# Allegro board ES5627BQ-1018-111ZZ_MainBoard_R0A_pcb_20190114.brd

Outline 269.65 x 263.7 mm; copper layers: TOP, G2, V3, G4, S5, G6, S7, G8, S9, G10, G11, S12, G13, S14, G15, S16, G17, V18, G19, BOTTOM. Coordinates in mm from the lower left corner of the outline.
Outline path: circle c5.87,182.28 r1.75 ; circle c7.2,256.7 r1.75 ; circle c7.2,72.2 r1.5 ; circle c30.3,216.7 r1.75 ; circle c90.07,249.68 r2.11 ; circle c91.46,145.41 r1.75 ; circle c98.58,71.61 r1.75 ; circle c129.84,140.5 r1.75 ; circle c129.84,227.5 r1.75 ; circle c139.67,112.11 r1.75 ; circle c139.67,86.07 r1.75 ; circle c144.65,258.7 r1.75 ; circle c163.36,207.2 r1.75 ; circle c191.36,163.2 r1.75 ; circle c200.12,112.11 r1.75 ; circle c200.12,86.07 r1.75 ; circle c205.84,140.5 r1.75 ; circle c216.84,227.5 r1.75 ; circle c246.84,227.5 r1.75 ; circle c246.84,140.5 r1.75 ; circle c264.65,258.7 r1.75 ; circle c264.65,178.7 r1.75 ; circle c264.65,98.7 r1.75 ; circle c264.95,52.61 r1.5 ; 265.13,257.02 262.97,259.18 ; 0,262.5 arc(0.35,263.35) 1.2,263.7 268.45,263.7 arc(269.3,263.35) 269.65,262.5 269.65,1.2 arc(269.3,0.35) 268.45,0 219.3,0 219.3,4.8 arc(218.95,5.65) 218.1,6 200.77,6 199.7,7.27 arc(199.02,7.58) 198.56,7 198.56,4.8 197.36,3 113.41,3 112.21,4.8 112.21,7 arc(111.61,7.6) 111.01,7 111.01,4.8 109.81,3 23.96,3 arc(23.11,3.35) 22.76,4.2 22.76,4.8 arc(22.41,5.65) 21.56,6 4.5,6 arc(3.65,5.65) 3.3,4.8 3.3,0 1.2,0 arc(0.35,0.35) 0,1.2 0,262.5

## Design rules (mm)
net group 1PPS_OUT_N: nets 1PPS_OUT_N 1PPS_OUT_N_R
net group 1PPS_OUT_P: nets 1PPS_OUT_P 1PPS_OUT_P_R
net group 1PPS_OUT_P_A: nets 1PPS_OUT_N_A 1PPS_OUT_P_A
net group 1PPS_RESERVE: nets 1PPS_RESERVE 1PPS_RESERVE_R
net group 1588_UART_FROM_CPU: nets 1588_CPU_OUT 1588_UART_FROM_CPU
net group 1588_UART_TO_CPU: nets 1588_TO_CPU 1588_UART_TO_CPU
net group 33931_SCL_R: nets 33931_SCL 33931_SCL_R
net group 33931_SDA_R: nets 33931_SDA 33931_SDA_R
net group 88470_1588_I2C_SDA: nets 88470_1588_I2C_SDA MAC_CPU_I2C_SDA
net group 88470_I2C_SCL: nets 88470_I2C_SCL 88470_I2C_SCL_R
net group BCM88470_LED_CLK: nets BCM88470_LED_CLK IP_LED_CLK0
net group BCM88470_LED_DATA: nets BCM88470_LED_DATA IP_LED_DATA0
net group BITS_XFMR_TTIP: nets BITS_TTIP BITS_XFMR_TTIP
net group BOOT9_5: nets BOOT9_5 BOOT__R8_5_R
net group BOOT9_6: nets BOOT9_6 BOOT__R8_6_R
net group BU_CPLD2_TDO: nets BU_CPLD2_TDO BU_CPLD2_TDO_R
net group BUS_DDRA-CLK: nets DDRA_CK_N DDRA_CK_P
net group BUS_DDRA-CMD: nets DDRA_ALERT0 DDRA_ALERT1
net group BUS_DDRB-CLK: nets DDRB_CK_N DDRB_CK_P
net group BUS_DDRB-CMD: nets DDRB_ALERT0 DDRB_ALERT1
net group BUS_DDRC-CLK: nets DDRC_CK_N DDRC_CK_P
net group BUS_DDRC-CMD: nets DDRC_ALERT0 DDRC_ALERT1
net group CLK_BITS_OSC_MCLK: nets CLK_BITS_OSC_MCLK CLK_BITS_OSC_R
net group CLS_GND: nets MGMT_PHY_MDI_N0_R MGMT_PHY_MDI_P0_R
net group CONN_JTAG_TCK: nets CONN_JTAG_TCK JTAG_TCK
net group CONN_JTAG_TDI: nets CONN_JTAG_TDI JTAG_TDO
net group CONN_JTAG_TDO: nets CONN_JTAG_TDO JTAG_TDI
net group CPLD1_TCK_R: nets CPLD1_TCK_R FPGA_JTAG_TCK
net group CPLD1_TMS_R: nets CPLD1_TMS_R FPGA_JTAG_TMS
net group CPLD2_25M_OUT_R: nets CPLD2_25M_OUT CPLD2_25M_OUT_R
net group CPLD2_TDO: nets CPLD2_TDO JTAG_CPLD2_TDO_R
net group CPLD_VDD1P8_PG_R: nets CPLD_VDD1P8_PG CPLD_VDD1P8_PG_R
net group CPLL_25M_R_CLK_N: nets CPLL_25M_R_CLK_N CPLL_25M_REFCLK_N
net group CPLL_25M_R_CLK_P: nets CPLL_25M_R_CLK_P CPLL_25M_REFCLK_P
net group CPU_CTS_N: nets CPU_CTS_N CPU_CTS_N_A
net group CPU_FPGA_PCIE_REFCLK_N: nets CPU_FPGA_PCIE_REFCLK_N N63368769
net group CPU_FPGA_PCIE_REFCLK_P: nets CPU_FPGA_PCIE_REFCLK_P N63368767
net group CPU_MPHY_MDC: nets CPU_MPHY_MDC CPU_MPHY_MDC_R
net group CPU_MPHY_MDIO: nets CPU_MPHY_MDIO CPU_MPHY_MDIO_R
net group CPU_RS232_C1+: nets CPU_RS232_C1+ CPU_RS232_C1-
net group CPU_RS232_C2+: nets CPU_RS232_C2+ CPU_RS232_C2-
net group CPU_RS232_TXD: nets CPU_RS232_TXD FPGA_UART1_TX
net group CPU_RTS_N: nets CPU_RTS_N CPU_RTS_N_A
net group CPU_RXD: nets CPU_RXD CPU_RXD_A
net group CPU_TXD: nets CPU_TXD CPU_TXD_A
net group DDR_GEN_XTAL_OUT: nets DDR_GEN_XTAL_OUT DDR_GEN_XTAL_OUT_R
net group DIFF_1PPS_OUT__A_R: nets 1PPS_OUT_N_A_R 1PPS_OUT_P_A_R
net group DIFF_HSDAC_: nets HSDAC_N HSDAC_P
net group DIFF_MGMT_PHY_MDI: nets MGMT_PHY_MDI_N3_R MGMT_PHY_MDI_P3_R
net group DIFF_NIF__RX00: nets NIF_N_RX00 NIF_P_RX00
net group DIFF_NIF__RX01: nets NIF_N_RX01 NIF_P_RX01
net group DIFF_NIF__RX02: nets NIF_N_RX02 NIF_P_RX02
net group DIFF_NIF__RX03: nets NIF_N_RX03 NIF_P_RX03
net group DIFF_NIF__RX04: nets NIF_N_RX04 NIF_P_RX04
net group DIFF_NIF__RX05: nets NIF_N_RX05 NIF_P_RX05
net group DIFF_NIF__RX06: nets NIF_N_RX06 NIF_P_RX06
net group DIFF_NIF__RX07: nets NIF_N_RX07 NIF_P_RX07
net group DIFF_NIF__TX00: nets NIF_N_TX00 NIF_P_TX00
net group DIFF_NIF__TX01: nets NIF_N_TX01 NIF_P_TX01
net group DIFF_NIF__TX02: nets NIF_N_TX02 NIF_P_TX02
net group DIFF_NIF__TX03: nets NIF_N_TX03 NIF_P_TX03
net group DIFF_NIF__TX04: nets NIF_N_TX04 NIF_P_TX04
net group DIFF_NIF__TX05: nets NIF_N_TX05 NIF_P_TX05
net group DIFF_NIF__TX06: nets NIF_N_TX06 NIF_P_TX06
net group DIFF_NIF__TX07: nets NIF_N_TX07 NIF_P_TX07
net group DIFF_NIF_RX[08]: nets NIF_RX[11]_N NIF_RX[11]_P
net group DIFF_NIF_RX[09]: nets NIF_RX[09]_N NIF_RX[09]_P
net group DIFF_NIF_RX[10]: nets NIF_RX[10]_N NIF_RX[10]_P
net group DIFF_NIF_RX[11]: nets NIF_RX[08]_N NIF_RX[08]_P
net group DIFF_NIF_RX[12]: nets NIF_RX[13]_N NIF_RX[13]_P
net group DIFF_NIF_RX[13]: nets NIF_RX[15]_N NIF_RX[15]_P
net group DIFF_NIF_RX[14]: nets NIF_RX[12]_N NIF_RX[12]_P
net group DIFF_NIF_RX[15]: nets NIF_RX[14]_N NIF_RX[14]_P
net group DIFF_NIF_TX[08]: nets NIF_TX[08]_N NIF_TX[08]_P
net group DIFF_NIF_TX[09]: nets NIF_TX[09]_N NIF_TX[09]_P
net group DIFF_NIF_TX[10]: nets NIF_TX[10]_N NIF_TX[10]_P
net group DIFF_NIF_TX[11]: nets NIF_TX[11]_N NIF_TX[11]_P
net group DIFF_NIF_TX[12]: nets NIF_TX[12]_N NIF_TX[12]_P
net group DIFF_NIF_TX[13]: nets NIF_TX[13]_N NIF_TX[13]_P
net group DIFF_NIF_TX[14]: nets NIF_TX[14]_N NIF_TX[14]_P
net group DIFF_NIF_TX[15]: nets NIF_TX[15]_N NIF_TX[15]_P
net group DIFF_NIFE_RX[16]: nets NIFE_RX[16]_N NIFE_RX[16]_P
net group DIFF_NIFE_RX[17]: nets NIFE_RX[17]_N NIFE_RX[17]_P
net group DIFF_NIFE_RX[18]: nets NIFE_RX[18]_N NIFE_RX[18]_P
net group DIFF_NIFE_RX[19]: nets NIFE_RX[19]_N NIFE_RX[19]_P
net group DIFF_NIFE_RX[20]: nets NIFE_RX[20]_N NIFE_RX[20]_P
net group DIFF_NIFE_RX[21]: nets NIFE_RX[21]_N NIFE_RX[21]_P
net group DIFF_NIFE_RX[22]: nets NIFE_RX[22]_N NIFE_RX[22]_P
net group DIFF_NIFE_RX[23]: nets NIFE_RX[23]_N NIFE_RX[23]_P
net group DIFF_NIFE_RX[24]: nets NIFE_RX[24]_N NIFE_RX[24]_P
net group DIFF_NIFE_RX[25]: nets NIFE_RX[25]_N NIFE_RX[25]_P
net group DIFF_NIFE_RX[26]: nets NIFE_RX[26]_N NIFE_RX[26]_P
net group DIFF_NIFE_RX[27]: nets NIFE_RX[27]_N NIFE_RX[27]_P
net group DIFF_NIFE_TX[16]: nets NIFE_TX[16]_N NIFE_TX[16]_P
net group DIFF_NIFE_TX[17]: nets NIFE_TX[17]_N NIFE_TX[17]_P
net group DIFF_NIFE_TX[18]: nets NIFE_TX[18]_N NIFE_TX[18]_P
net group DIFF_NIFE_TX[19]: nets NIFE_TX[19]_N NIFE_TX[19]_P
net group DIFF_NIFE_TX[20]: nets NIFE_TX[20]_N NIFE_TX[20]_P
net group DIFF_NIFE_TX[21]: nets NIFE_TX[21]_N NIFE_TX[21]_P
net group DIFF_NIFE_TX[22]: nets NIFE_TX[22]_N NIFE_TX[22]_P
net group DIFF_NIFE_TX[23]: nets NIFE_TX[23]_N NIFE_TX[23]_P
net group DIFF_NIFE_TX[24]: nets NIFE_TX[24]_N NIFE_TX[24]_P
net group DIFF_NIFE_TX[25]: nets NIFE_TX[25]_N NIFE_TX[25]_P
net group DIFF_NIFE_TX[26]: nets NIFE_TX[26]_N NIFE_TX[26]_P
net group DIFF_NIFE_TX[27]: nets NIFE_TX[27]_N NIFE_TX[27]_P
net group DIFF_NIFE_TX[46]: nets 10G_KR_RX1_N 10G_KR_RX1_P
net group DIFF_NIFE_TX[47]: nets 10G_KR_RX0_N 10G_KR_RX0_P
net group DIFF_THERMAL_DIODE__R: nets THERMAL_DIODE_N_R THERMAL_DIODE_P_R
net group DIFFPAIR1: nets MGMT_PHY_MDI_N2_R MGMT_PHY_MDI_P2_R
net group DIFFPAIR2: nets MGMT_PHY_MDI_N1_R MGMT_PHY_MDI_P1_R
net group DIFFPAIR4: nets MGMT_MDI_N0_GE MGMT_MDI_P0_GE
net group DIFFPAIR5: nets MGMT_MDI_N1_GE MGMT_MDI_P1_GE
net group DIFFPAIR6: nets MGMT_MDI_N2_GE MGMT_MDI_P2_GE
net group DIFFPAIR7: nets MGMT_MDI_N3_GE MGMT_MDI_P3_GE
net group DIFFPAIR8: nets RJ_STACKING_SYNC_N0 RJ_STACKING_SYNC_P0
net group DIFFPAIR9: nets RJ_STACKING_SYNC_N1 RJ_STACKING_SYNC_P1
net group DIFFPAIR10: nets RJ_STACKING_SYNC_N2 RJ_STACKING_SYNC_P2
net group DIFFPAIR11: nets RJ_STACKING_SYNC_N3 RJ_STACKING_SYNC_P3
net group DIFFPAIR20: nets STACKING_CNTL_MDI_N3_GE STACKING_CNTL_MDI_P3_GE
net group DIFFPAIR21: nets STACKING_CNTL_MDI_N2_GE STACKING_CNTL_MDI_P2_GE
net group DIFFPAIR22: nets STACKING_CNTL_MDI_N1_GE STACKING_CNTL_MDI_P1_GE
net group DIFFPAIR23: nets STACKING_CNTL_MDI_N0_GE STACKING_CNTL_MDI_P0_GE
net group DIFFPAIR24: nets MGMT_PHY_MDI_N0 MGMT_PHY_MDI_P0
net group DIFFPAIR25: nets MGMT_PHY_MDI_N3 MGMT_PHY_MDI_P3
net group DIFFPAIR26: nets MGMT_PHY_MDI_N2 MGMT_PHY_MDI_P2
net group DIFFPAIR27: nets MGMT_PHY_MDI_N1 MGMT_PHY_MDI_P1
net group DIFFPAIR29: nets SATA0_RX_N SATA0_RX_P
net group DIFFPAIR31: nets FC1_156.25M_REFCLKN_R FC1_156.25M_REFCLKP_R
net group DIFFPAIR32: nets FC2_156.25M_REFCLKN_R FC2_156.25M_REFCLKP_R
net group DIFFPAIR33: nets FPGA_156.25M_REF_CLK_N_R FPGA_156.25M_REF_CLK_P_R
net group DIFFPAIR43: nets BITS_RRING BITS_RTIP
net group DIFFPAIR45: nets BITS_TRING_R BITS_XFMR_TTIP_R
net group DIFFPAIR46: nets BITS_RRING_R BITS_RTIP_R
net group DIFFPAIR48: nets N62472864 N62472867
net group DIFFPAIR49: nets USB2_N USB2_P
net group DIFFPAIR50: nets CPU_FPGA_PCIE_TX_N CPU_FPGA_PCIE_TX_P
net group DIFFPAIR53: nets N62747426 N62747432
net group DIFFPAIR54: nets N62747438 N62747447
net group DIFFPAIR55: nets FPGA_156.25M_REF_CLK_N FPGA_156.25M_REF_CLK_P
net group DIFFPAIR58: nets P_STACKING_SYNC_N1 P_STACKING_SYNC_P1
net group DIFFPAIR59: nets P_STACKING_SYNC_N0 P_STACKING_SYNC_P0
net group DIFFPAIR60: nets P_STACKING_SYNC_N3 P_STACKING_SYNC_P3
net group DIFFPAIR61: nets P_STACKING_SYNC_N2 P_STACKING_SYNC_P2
net group DIFFPAIR62: nets FPGA_156.25M_REF_CLK_N_F FPGA_156.25M_REF_CLK_P_F
net group DP_TS_25M_REFCLK_N_R: nets TS_25M_REFCLK_N_R TS_25M_REFCLK_P_R
net group EEPROM_SCL: nets EEPROM_SCL EEPROM_SCL_R
net group EEPROM_SDA: nets EEPROM_SDA EEPROM_SDA_R
net group EN_VDD1P0_ROV: nets EN_VDD1P0_ROV VEN_VDD1P0_ROV
net group FAN_SCL_1: nets FAN_SCL_1 FAN_SCL_FPGA
net group FAN_SDA_1: nets FAN_SDA_1 FAN_SDA_FPGA
net group FAP_SYNC1: nets FAP_SYNC1 FAP_SYNC1_R
net group FAP_TIME_VAL0: nets FAP_TIME_VAL0 FAP_TIME_VAL0_R
net group FAP_TIME_VAL1: nets FAP_TIME_VAL1 FAP_TIME_VAL1_R
net group FAP_TS_BIT_CLK0: nets FAP_TS_BIT_CLK0 TS_BIT_CLK0_R
net group FAP_TS_BIT_CLK1: nets FAP_TS_BIT_CLK1 TS_BIT_CLK1_R
net group FPGA_CPU_PCIE_RX_N: nets FPGA_CPU_PCIE_RX_N FPGA_CPU_PCIE_RX_N_F
net group FPGA_CPU_PCIE_RX_P: nets FPGA_CPU_PCIE_RX_P FPGA_CPU_PCIE_RX_P_F
net group FPGA_JTAG_TDO: nets FPGA_JTAG_TDO JTAG_CPLD2_TDI
net group GPS_UART_RX: nets GPS_UART_RX GPS_UART_RX_R
net group I2C_0_SCL_CPLD2: nets I2C_0_SCL_CPLD2 I2C_0_SCL_SWITCH_CPLD2_R
net group I2C_0_SCL_SWITCH_CPLD1_R: nets I2C_0_SCL_CPLD1 I2C_0_SCL_SWITCH_CPLD1_R
net group I2C_0_SDA: nets I2C_0_SDA I2C_0_SDA_R
net group I2C_1_SDA: nets I2C_1_SDA I2C_1_SDA_R
net group L1_RCVRD_CLK: nets L1_RCVRD_CLK L1_RCVRD_CLK_R
net group L1_RCVRD_CLK_BKUP: nets L1_RCVRD_CLK_BKUP L1_RCVRD_CLK_BKUP_R
net group L1_RCVRD_CLK_BKUP_G: nets L1_RCVRD_CLK_BKUP_G L1_RCVRD_CLK_BKUP_GR
net group L1_RCVRD_CLK_G: nets L1_RCVRD_CLK_G L1_RCVRD_CLK_GR
net group L1_RCVRD_CLK_VALID: nets L1_RCVRD_CLK_VALID L1_RCVRD_CLK_VALID_R
net group L1_RCVRD_CLK_VALID_BKUP: nets L1_RCVRD_CLK_VALID_BKUP L1_RCVRD_CLK_VALID_BKUP_R
net group LED_LINK1000: nets LED_LINK1000 MGMT_PHY_LINK_LED
net group LED_TX: nets LED_TX MGMT_PHY_ACT_LED
net group LM75BD1_INT: nets LM75BD1_INT LM75BD1_INT_R
net group LM75BD1_SCLK_R: nets LM75BD1_SCLK LM75BD1_SCLK_R
net group LM75BD1_SDA: nets LM75BD1_SDA LM75BD1_SDA_R
net group LM75BD2_INT: nets LM75BD2_INT LM75BD2_INT_R
net group LM75BD2_SDA: nets LM75BD2_SDA LM75BD2_SDA_R
net group LM75BD3_INT: nets LM75BD3_INT LM75BD3_INT_R
net group LM75BD3_SCLK_R: nets LM75BD3_SCLK LM75BD3_SCLK_R
net group LM75BD3_SDA: nets LM75BD3_SDA LM75BD3_SDA_R
net group MAC_25M_OUT: nets MAC_25M_OUT MAC_25M_OUT_R
net group MAC_JTAG_TCK: nets MAC_JTAG_TCK MAC_TCK
net group MAC_NIF_156.25M_N: nets MAC_NIF_156.25M_N NIF_156.25M_N
net group MAC_NIF_156.25M_P: nets MAC_NIF_156.25M_P NIF_156.25M_P
net group MAC_NIFE1_156.25M_N: nets MAC_NIFE1_156.25M_N NIFE1_156.25M_N
net group MAC_NIFE1_156.25M_P: nets MAC_NIFE1_156.25M_P NIFE1_156.25M_P
net group MAC_PCIE_100M_MAC_N: nets MAC_PCIE_100M_MAC_N MAC_PCIE_100M_N
net group MAC_PCIE_100M_MAC_P: nets MAC_PCIE_100M_MAC_P MAC_PCIE_100M_P
net group MAC_TDO: nets MAC_JTAG_TDO MAC_TDO
net group MAC_TRST: nets MAC_TCE MAC_TRST
net group MANG_1P2_PG_R: nets MANG_1P2_PG MANG_1P2_PG_R
net group MGMT_MDI_N0: nets MGMT_MDI_N0 MGMT_MDI_N0_R
net group MGMT_MDI_N1: nets MGMT_MDI_N1 MGMT_MDI_N1_R
net group MGMT_MDI_N2: nets MGMT_MDI_N2 MGMT_MDI_N2_R
net group MGMT_MDI_N3: nets MGMT_MDI_N3 MGMT_MDI_N3_R
net group MGMT_MDI_P0: nets MGMT_MDI_P0 MGMT_MDI_P0_R
net group MGMT_MDI_P1: nets MGMT_MDI_P1 MGMT_MDI_P1_R
net group MGMT_MDI_P2: nets MGMT_MDI_P2 MGMT_MDI_P2_R
net group MGMT_MDI_P3: nets MGMT_MDI_P3 MGMT_MDI_P3_R
net group NIFE_RX[32]: nets NIFE_RX[32]_N NIFE_RX[32]_P
net group NIFE_RX[33]: nets NIFE_RX[33]_N NIFE_RX[33]_P
net group NIFE_RX[34]: nets NIFE_RX[34]_N NIFE_RX[34]_P
net group NIFE_RX[35]: nets NIFE_RX[35]_N NIFE_RX[35]_P
net group NIFE_RX[36]: nets NIFE_RX[36]_N NIFE_RX[36]_P
net group NIFE_RX[37]: nets NIFE_RX[37]_N NIFE_RX[37]_P
net group NIFE_RX[38]: nets NIFE_RX[38]_N NIFE_RX[38]_P
net group NIFE_RX[39]: nets NIFE_RX[39]_N NIFE_RX[39]_P
net group NIFE_RX[46]_N: nets 10G_KR_TX1_N NIFE_RX[46]_N
net group NIFE_RX[46]_P: nets 10G_KR_TX1_P NIFE_RX[46]_P
net group NIFE_RX[47]_N: nets 10G_KR_TX0_N NIFE_RX[47]_N
net group NIFE_RX[47]_P: nets 10G_KR_TX0_P NIFE_RX[47]_P
net group NIFE_TX[32]: nets NIFE_TX[32]_N NIFE_TX[32]_P
net group NIFE_TX[33]: nets NIFE_TX[33]_N NIFE_TX[33]_P
net group NIFE_TX[34]: nets NIFE_TX[34]_N NIFE_TX[34]_P
net group NIFE_TX[35]: nets NIFE_TX[35]_N NIFE_TX[35]_P
net group NIFE_TX[36]: nets NIFE_TX[36]_N NIFE_TX[36]_P
net group NIFE_TX[37]: nets NIFE_TX[37]_N NIFE_TX[37]_P
net group NIFE_TX[38]: nets NIFE_TX[38]_N NIFE_TX[38]_P
net group NIFE_TX[39]: nets NIFE_TX[39]_N NIFE_TX[39]_P
net group OCXO25MHZ: nets OCXO25MHZ OCXO25MHZ_R
net group PEX_CPU_PCIEA_RX_0_N: nets PEX_CPU_PCIEA_RX_0_C_N PEX_CPU_PCIEA_RX_0_N
net group PEX_CPU_PCIEA_RX_0_P: nets PEX_CPU_PCIEA_RX_0_C_P PEX_CPU_PCIEA_RX_0_P
net group PHY_TDI: nets PHY_TDI PHY_TDI_R
net group PHY_TDO: nets PHY_TDO PHY_TDO_R
net group PM_VDDQ_EN_R: nets PM_VDDQ_EN_R VEN_VDD0P6
net group PSU1_SCL: nets PSU1_SCL PSU1_SCL_R
net group PSU1_SDA: nets PSU1_SDA PSU1_SDA_R
net group PSU2_SCL: nets PSU2_SCL PSU2_SCL_R
net group PSU2_SDA: nets PSU2_SDA PSU2_SDA_R
net group PSU_MONITOR_SCL: nets PSU_MONITOR_SCL PSU_MONITOR_SCL_R
net group QSFP_INT_P02: nets QSFP_INT_P02 QSFP_INT_P02_R
net group QSFP_INT_P03: nets QSFP_INT_P03 QSFP_INT_P03_R
net group QSFP_P01_SCL: nets QSFP_P01_SCL QSFP_P01_SCL_R
net group QSFP_P01_SDA_R: nets QSFP_P01_SDA QSFP_P01_SDA_R
net group QSFP_P02_SCL: nets QSFP_P02_SCL QSFP_P02_SCL_R
net group QSFP_P02_SDA_R: nets QSFP_P02_SDA QSFP_P02_SDA_R
net group SFP+_P01_SCL_R: nets SFP+_P01_SCL SFP+_P01_SCL_R
net group SFP+_P01_SDA_R: nets SFP+_P01_SDA SFP+_P01_SDA_R
net group SFP+_P02_SCL_R: nets SFP+_P02_SCL SFP+_P02_SCL_R
net group SFP+_P02_SDA_R: nets SFP+_P02_SDA SFP+_P02_SDA_R
net group SFP+_P03_SCL_R: nets SFP+_P03_SCL SFP+_P03_SCL_R
net group SFP+_P03_SDA_R: nets SFP+_P03_SDA SFP+_P03_SDA_R
net group SFP+_P04_SCL_R: nets SFP+_P04_SCL SFP+_P04_SCL_R
net group SFP+_P04_SDA_R: nets SFP+_P04_SDA SFP+_P04_SDA_R
net group SFP+_P05_SCL_R: nets SFP+_P05_SCL SFP+_P05_SCL_R
net group SFP+_P05_SDA_R: nets SFP+_P05_SDA SFP+_P05_SDA_R
net group SFP+_P06_SCL_R: nets SFP+_P06_SCL SFP+_P06_SCL_R
net group SFP+_P06_SDA_R: nets SFP+_P06_SDA SFP+_P06_SDA_R
net group SFP+_P07_SCL_R: nets SFP+_P07_SCL SFP+_P07_SCL_R
net group SFP+_P07_SDA_R: nets SFP+_P07_SDA SFP+_P07_SDA_R
net group SFP+_P08_SCL_R: nets SFP+_P08_SCL SFP+_P08_SCL_R
net group SFP+_P08_SDA_R: nets SFP+_P08_SDA SFP+_P08_SDA_R
net group SFP+_P09_SCL_R: nets SFP+_P09_SCL SFP+_P09_SCL_R
net group SFP+_P09_SDA_R: nets SFP+_P09_SDA SFP+_P09_SDA_R
net group SFP+_P10_SCL_R: nets SFP+_P10_SCL SFP+_P10_SCL_R
net group SFP+_P10_SDA_R: nets SFP+_P10_SDA SFP+_P10_SDA_R
net group SFP+_P11_SCL_R: nets SFP+_P11_SCL SFP+_P11_SCL_R
net group SFP+_P11_SDA_R: nets SFP+_P11_SDA SFP+_P11_SDA_R
net group SFP+_P12_SCL_R: nets SFP+_P12_SCL SFP+_P12_SCL_R
net group SFP+_P12_SDA_R: nets SFP+_P12_SDA SFP+_P12_SDA_R
net group SFP+_P13_SCL_R: nets SFP+_P13_SCL SFP+_P13_SCL_R
net group SFP+_P13_SDA_R: nets SFP+_P13_SDA SFP+_P13_SDA_R
net group SFP+_P14_SCL_R: nets SFP+_P14_SCL SFP+_P14_SCL_R
net group SFP+_P14_SDA_R: nets SFP+_P14_SDA SFP+_P14_SDA_R
net group SFP+_P15_SCL_R: nets SFP+_P15_SCL SFP+_P15_SCL_R
net group SFP+_P15_SDA_R: nets SFP+_P15_SDA SFP+_P15_SDA_R
net group SFP+_P16_SCL_R: nets SFP+_P16_SCL SFP+_P16_SCL_R
net group SFP+_P16_SDA_R: nets SFP+_P16_SDA SFP+_P16_SDA_R
net group SFP+_P17_SCL_R: nets SFP+_P17_SCL SFP+_P17_SCL_R
net group SFP+_P17_SDA_R: nets SFP+_P17_SDA SFP+_P17_SDA_R
net group SFP+_P18_SCL_R: nets SFP+_P18_SCL SFP+_P18_SCL_R
net group SFP+_P18_SDA_R: nets SFP+_P18_SDA SFP+_P18_SDA_R
net group SFP+_P19_SCL: nets SFP+_P19_SCL SFP+_P19_SCL_R
net group SFP+_P19_SDA: nets SFP+_P19_SDA SFP+_P19_SDA_R
net group SFP+_P20_SCL_R: nets SFP+_P20_SCL SFP+_P20_SCL_R
net group SFP+_P20_SDA_R: nets SFP+_P20_SDA SFP+_P20_SDA_R
net group SFP+_P21_SCL_R: nets SFP+_P21_SCL SFP+_P21_SCL_R
net group SFP+_P21_SDA_R: nets SFP+_P21_SDA SFP+_P21_SDA_R
net group SFP+_P22_SCL_R: nets SFP+_P22_SCL SFP+_P22_SCL_R
net group SFP+_P22_SDA_R: nets SFP+_P22_SDA SFP+_P22_SDA_R
net group SFP+_P23_SCL_R: nets SFP+_P23_SCL SFP+_P23_SCL_R
net group SFP+_P23_SDA_R: nets SFP+_P23_SDA SFP+_P23_SDA_R
net group SP01_P08_SCL: nets SP01_P08_SCL SP01_P08_SCL_R
net group SP09_P16_SCL: nets SP09_P16_SCL SP09_P16_SCL_R
net group SP17_P24_SCL: nets SP17_P24_SCL SP17_P24_SCL_R
net group TPS53641_SDA_R: nets TPS53641_SDA_R VCC1V0_PMB_DIO
net group TS_25M_REFCLK_MAC_N: nets TS_25M_REFCLK_MAC_N TS_25M_REFCLK_N
net group TS_25M_REFCLK_MAC_P: nets TS_25M_REFCLK_MAC_P TS_25M_REFCLK_P
net group UART1_RX: nets CPLD_UART1_RX_R UART1_RX
net group UART1_TX: nets CPU_UART1_TX_R UART1_TX
net group UART_TX+: nets UART_TX+ UART_TX+_R
net group UART_TX+_A: nets UART_TX+_A UART_TX-_A
net group UART_TX-: nets UART_TX- UART_TX-_R
net group UC_25M_R_CLK_N: nets UC_25M_R_CLK_N UC_25M_REFCLK_N
net group UC_25M_R_CLK_P: nets UC_25M_R_CLK_P UC_25M_REFCLK_P
net group UCD90160_CNTRL: nets UCD90160_CNTRL UCD90160_CNTRL_R
net group UCD90160_INT: nets UCD90160_INT UCD90160_INT_R
net group UCD90160_RESERVED: nets UCD90160_RESERVED UCD90160_RESERVED_R
net group UCD90160_RST: nets HW_RESET UCD90160_RST
net group UCD90160_SCL_R: nets UCD90160_SCL UCD90160_SCL_R
net group UCD90160_SDA_R: nets UCD90160_SDA UCD90160_SDA_R
net group USBHUB_OCS1_N: nets USB_PWRFLT_N USBHUB_OCS1_N
net group USBHUB_PRTPWR1: nets USB_PWRON_N USBHUB_PRTPWR1
net group USBHUB_SDA: nets I2C_USBHUB_SDA_R USBHUB_SDA
net group USBHUB_XTALOUT_C: nets USBHUB_XTALOUT USBHUB_XTALOUT_C
net group VCC1V0_VSN: nets TPS53647_GND_SENSE VCC1V0_VSN
net group VCC1V0_VSP: nets TPS53647_VDD_SENSE VCC1V0_VSP
net group VCC1V2_BST_C: nets VCC1V2_BST_C VCC1V2_VBST
net group VCC1V2_EN: nets VCC1V2_EN VEN_VDD1P2_DDR
net group VCC1V_ENABLE: nets VCC1V_ENABLE VEN_VDD1P0
net group VCC1V_LL_C: nets VCC1V_LL_C VCC1V_VBST
net group VCC2V5_EN: nets VCC2V5_EN VEN_VPP_DDR2P5
net group VCC3V3_PCH_EN_R: nets VCC3V3_PCH_EN_R VEN_VDD3P3
net group VCC3V3_PCH_VFB_S: nets VCC3V3_PCH_VFB_S VCC3V3_TAP
net group VDD1P25_PG_R: nets VDD1P25_PG VDD1P25_PG_R
net group VEN_VCC5P0_R: nets VEN_VCC5P0_FPGA VEN_VCC5P0_R
net group VEN_VDD1P8_R: nets VEN_VDD1P8 VEN_VDD1P8_R
net group VEN_VDD1P25_R: nets VEN_VDD1P25 VEN_VDD1P25_R
net group 88470_1588_I2C_SCL: nets 88470_1588_I2C_SCL MAC_CPU_I2C_SCL MASTER_I2C_SCL
net group BCM88470_THERM_DIODE_VDD3P3: nets BCM88470_THERM_DIODE_VDD3P3
net group BITS_CHOKE_RRING: nets BITS_RJ48_RRING
net group BITS_CHOKE_RTIP: nets BITS_RJ48_RTIP
net group BITS_CHOKE_TRING: nets BITS_RJ48_TRING
net group BITS_CHOKE_TTIP: nets BITS_RJ48_TTIP
net group BUS_CLK: nets 1PPS_FPGA_IN 25MHZ_1PPS_FPGA_IN 25MHZ_1PPS_FPGA_IN_R 25MHZ_1204 25MHZ_30773 25MHZ_30773_R BCM88470_NIF_LCPLL_BYP_CLK BCM88470_NIFE_LCPLL0_BYP_CLK BCM88470_NIFE_LCPLL1_BYP_CLK COM_LPC_CLK CPLD_RST CPU_PROCHOT FPGA_REF_CLK0 FPGA_REF_CLK0_R FPGA_REF_CLK1 FPGA_REF_CLK1_R FPGA_REF_CLK2 FPGA_REF_CLK2_R FPGA_REF_CLK3 FPGA_REF_CLK3_R FPGA_REF_CLK_OUT0 FPGA_REF_CLK_OUT1 FPGA_REF_CLK_OUT2 FPGA_REF_CLK_OUT3 FPGA_RES_CLK FPGA_RES_CLK_R FPGA_SN65C_1DE FPGA_SPI_RST_N FT2232H_RESET_N I2C_CPU0_RESET_N I2C_CPU1_RESET_N LM75BD1_SCLK_C LM75BD3_SCLK_C MAC_RESET_N MGMT_CLK_IN MGMT_CLK_IN_R N62370066 N62745262 PHY_RST_N PHY_RST_N_R PHY_TCK PHY_TCK_R PHY_TMS PHY_TMS_R PHY_TRST_N POWER_RST POWER_RST_S PSU_MONITOR_RESET_N QSFP_PRSNT_P02 RXSCLK_SET SATA0_TX_P SP01_P08_RESET_N SP09_P16_RESET_N SPI_CLK SYS_SW_RST_N TPM_RESET_N USB1_VBUS_RESET USB_RESET_N ZL30773_RST
net group BUS_CLK1: nets 2.048MHZ_BITS_RCLK_IN BITS_PCLK BITS_TCLK_R CLK_BITS_MCLK CLK_BITS_TCLK DDR_GEN_XTAL_IN FAP_TS_BIT_CLK0_FPGA FAP_TS_BIT_CLK1_FPGA USBHUB_XTALIN
net group BUS_DDRA-DATA: nets DDRA_DBI_N0 DDRA_DQS0_N DDRA_DQS0_P DDRA_DQS1_N DDRA_DQS1_P DDRA_DQS2_N DDRA_DQS2_P DDRA_DQS3_N DDRA_DQS3_P
net group BUS_DDRB-DATA: nets DDRB_DQS0_N DDRB_DQS0_P DDRB_DQS1_N DDRB_DQS1_P DDRB_DQS2_N DDRB_DQS2_P DDRB_DQS3_N DDRB_DQS3_P
net group BUS_DDRC-DATA: nets DDRC_DQS0_N DDRC_DQS0_P DDRC_DQS1_N DDRC_DQS1_P DDRC_DQS2_N DDRC_DQS2_P DDRC_DQS3_N DDRC_DQS3_P
net group BUS_I2C: nets 88470_I2C_SDA CPLD_FPGA_R_SCL CPLD_FPGA_R_SDA CPLD_FPGA_SCL CPLD_FPGA_SDA FAN_SCL_FPGA_R FAN_SDA_FPGA_R I2C_0_SCL I2C_1_SCL LM75BD2_SCLK LM75BD2_SCLK_C LM75BD2_SCLK_R QSFP_P03_SDA_R USBHUB_SCL USBHUB_SCL_R USBHUB_SDA_R VCC1V0_PMB_DIO_R
net group BUS_SPI: nets BCM88470_SPI_CLK BCM88470_SPI_MISO BCM88470_SPI_MOSI
net group CLS_BITS_S80: nets BITS_XFMR_R_RRING BITS_XFMR_R_RTIP BITS_XFMR_R_TRING BITS_XFMR_R_TTIP
net group CLS_CHASIS: nets GND_USB
net group CLS_DDRA_CTL: nets DDRA_CKE DDRA_CS_N0 DDRA_CS_N1 DDRA_ODT
net group CLS_DDRA_DATA1: nets DDRA_DBI_N1 DDRA_DQ8 DDRA_DQ9 DDRA_DQ10 DDRA_DQ11 DDRA_DQ12 DDRA_DQ13 DDRA_DQ14 DDRA_DQ15
net group CLS_DDRA_DATA2: nets DDRA_DBI_N2 DDRA_DQ16 DDRA_DQ17 DDRA_DQ18 DDRA_DQ19 DDRA_DQ20 DDRA_DQ21 DDRA_DQ22 DDRA_DQ23
net group CLS_DDRA_DATA3: nets DDRA_DBI_N3 DDRA_DQ24 DDRA_DQ25 DDRA_DQ26 DDRA_DQ27 DDRA_DQ28 DDRA_DQ29 DDRA_DQ30 DDRA_DQ31
net group CLS_DDRA_MA: nets DDRA_A0 DDRA_A1 DDRA_A2 DDRA_A3 DDRA_A4 DDRA_A5 DDRA_A6 DDRA_A7 DDRA_A8 DDRA_A9 DDRA_A10 DDRA_A11 DDRA_A12 DDRA_A13 DDRA_ACT_N DDRA_BA0 DDRA_BA1 DDRA_BG0 DDRA_CAS_N DDRA_PAR DDRA_RAS_N DDRA_RST_N DDRA_WE_N
net group CLS_DDRB_CTL: nets DDRB_CKE DDRB_CS_N0 DDRB_CS_N1 DDRB_ODT
net group CLS_DDRB_DATA0: nets DDRB_DBI_N0 DDRB_DQ0 DDRB_DQ1 DDRB_DQ2 DDRB_DQ3 DDRB_DQ4 DDRB_DQ5 DDRB_DQ6 DDRB_DQ7
net group CLS_DDRB_DATA1: nets DDRB_DBI_N1 DDRB_DQ8 DDRB_DQ9 DDRB_DQ10 DDRB_DQ11 DDRB_DQ12 DDRB_DQ13 DDRB_DQ14 DDRB_DQ15
net group CLS_DDRB_DATA2: nets DDRB_DBI_N2 DDRB_DQ16 DDRB_DQ17 DDRB_DQ18 DDRB_DQ19 DDRB_DQ20 DDRB_DQ21 DDRB_DQ22 DDRB_DQ23
net group CLS_DDRB_DATA3: nets DDRB_DBI_N3 DDRB_DQ24 DDRB_DQ25 DDRB_DQ26 DDRB_DQ27 DDRB_DQ28 DDRB_DQ29 DDRB_DQ30 DDRB_DQ31
net group CLS_DDRB_MA: nets DDRB_A0 DDRB_A1 DDRB_A2 DDRB_A3 DDRB_A4 DDRB_A5 DDRB_A6 DDRB_A7 DDRB_A8 DDRB_A9 DDRB_A10 DDRB_A11 DDRB_A12 DDRB_A13 DDRB_ACT_N DDRB_BA0 DDRB_BA1 DDRB_BG0 DDRB_CAS_N DDRB_PAR DDRB_RAS_N DDRB_RST_N DDRB_WE_N
net group CLS_DDRC_CTL: nets DDRC_CKE DDRC_CS_N0 DDRC_CS_N1 DDRC_ODT
net group CLS_DDRC_DATA0: nets DDRC_DBI_N0 DDRC_DQ0 DDRC_DQ1 DDRC_DQ2 DDRC_DQ3 DDRC_DQ4 DDRC_DQ5 DDRC_DQ6 DDRC_DQ7
net group CLS_DDRC_DATA1: nets DDRC_DBI_N1 DDRC_DQ8 DDRC_DQ9 DDRC_DQ10 DDRC_DQ11 DDRC_DQ12 DDRC_DQ13 DDRC_DQ14 DDRC_DQ15
net group CLS_DDRC_DATA2: nets DDRC_DBI_N2 DDRC_DQ16 DDRC_DQ17 DDRC_DQ18 DDRC_DQ19 DDRC_DQ20 DDRC_DQ21 DDRC_DQ22 DDRC_DQ23
net group CLS_DDRC_DATA3: nets DDRC_DBI_N3 DDRC_DQ24 DDRC_DQ25 DDRC_DQ26 DDRC_DQ27 DDRC_DQ28 DDRC_DQ29 DDRC_DQ30 DDRC_DQ31
net group CLS_DDRC_MA: nets DDRC_A0 DDRC_A1 DDRC_A2 DDRC_A3 DDRC_A4 DDRC_A5 DDRC_A6 DDRC_A7 DDRC_A8 DDRC_A9 DDRC_A10 DDRC_A11 DDRC_A12 DDRC_A13 DDRC_ACT_N DDRC_BA0 DDRC_BA1 DDRC_BG0 DDRC_CAS_N DDRC_PAR DDRC_RAS_N DDRC_RST_N DDRC_WE_N
net group CLS_I2C: nets 30773_SCL_FP 30773_SCL_FP_R 30773_SDA_FP 30773_SDA_FP_R QSFP_P03_SCL QSFP_P03_SCL_R QSFP_P03_SDA SP17_P24_RESET_N
net group CLS_JTAG: nets FPGA_JTAG_TCK_R FPGA_JTAG_TDI_R FPGA_JTAG_TDO_R FPGA_JTAG_TMS_R JTAG_BUFFER_OE_N MAC_JTAG_TCE
net group CLS_PHY_DMI: nets M_MCT1 M_MCT2 M_MCT3 M_MCT4 MCT1 MCT2 MCT3 MCT4 MDI-0 MDI-1 MDI-2 MDI-3 N61307888 N61983825
net group CLS_UART: nets MAC_UART0_RX MAC_UART0_RX_R MAC_UART0_TX_FPGA MAC_UART0_TX_FPGA_R MAC_UART0_TX_R MAC_UART1_RX MAC_UART1_RX_R MAC_UART1_TX MAC_UART1_TX_FPGA MAC_UART1_TX_R
net group CLS_VCC12: nets HEATER_VCC12
net group CONN_JTAG_TMS: nets CONN_JTAG_TMS
net group CPLD2_TCK: nets CPLD2_TCK CPLD2_TCK_R JTAG_CPLD2_TCK
net group CPLD2_TMS: nets CPLD2_TMS CPLD2_TMS_R JTAG_CPLD2_TMS
net group CPU_RS232_RXD: nets CPLD_RJ_UART_RX_R CPU_RS232_RXD RJ_UART_RX
net group DDRA_100M_REFCLK_N: nets DDR_GEN_OUT0_N DDRA_100M_N DDRA_100M_REFCLK_N
net group DDRA_100M_REFCLK_P: nets DDR_GEN_OUT0_P DDRA_100M_P DDRA_100M_REFCLK_P
net group DDRB_100M_REFCLK_N: nets DDR_GEN_OUT1_N DDRB_100M_N DDRB_100M_REFCLK_N
net group DDRB_100M_REFCLK_P: nets DDR_GEN_OUT1_P DDRB_100M_P DDRB_100M_REFCLK_P
net group DDRC_100M_REFCLK_N: nets DDR_GEN_OUT2_N DDRC_100M_N DDRC_100M_REFCLK_N
net group DDRC_100M_REFCLK_P: nets DDR_GEN_OUT2_P DDRC_100M_P DDRC_100M_REFCLK_P
net group DEFAULT: nets VEN_XFP_3V3
net group DIFFPAIR28: nets SATA0_TX_N
net group DIFFPAIR44: nets BITS_TRING
net group FCCM10_5: nets FCCM10_5 FCCM10_6 SKIP#_VCC1V0
net group FPGA_25M_REF_CLK_N: nets FPGA_25M_REF_CLK_N FPGA_25M_REF_CLK_N_F FPGA_25M_REF_CLK_N_R
net group FPGA_25M_REF_CLK_P: nets FPGA_25M_REF_CLK_P FPGA_25M_REF_CLK_P_F FPGA_25M_REF_CLK_P_R
net group I2C_0_SDA_CPLD1: nets I2C_0_SDA_CPLD1 I2C_0_SDA_CPLD1_R I2C_0_SDA_SWITCH_CPLD1_R
net group I2C_0_SDA_CPLD2: nets I2C_0_SDA_CPLD2 I2C_0_SDA_CPLD2_R I2C_0_SDA_SWITCH_CPLD2_R
net group MAC_NIFE0_156.25M_N: nets FC0_156.25M_REFCLKN_R MAC_NIFE0_156.25M_N NIFE0_156.25M_N
net group MAC_NIFE0_156.25M_P: nets FC0_156.25M_REFCLKP_R MAC_NIFE0_156.25M_P NIFE0_156.25M_P
net group NOISY: nets XFP_3V3_VDD
net group PSU_MONITOR_SDA: nets PSU_MONITOR_SDA PSU_MONITOR_SDA_R QSP01_P02_R_SDA
net group SENSITIVE: nets VCC3V3_PCH_TRIP XFP_3V3_PCH_RF XFP_3V3_PCH_TRIP
net group SP01_P08_R_SDA: nets SP01_P08_R_SDA SP01_P08_SDA SP01_P08_SDA_R
net group SP09_P16_R_SDA: nets SP09_P16_R_SDA SP09_P16_SDA SP09_P16_SDA_R
net group SP17_P24_R_SDA: nets SP17_P24_R_SDA SP17_P24_SDA SP17_P24_SDA_R
net group TPS53641_SCL_R: nets TPS53641_SCL_R VCC1V0_PMB_CLK VCC1V0_PMB_CLK_R
net group USB_DM: nets USB0_N USB_DM USBHUB_DM
net group USB_DP: nets USB0_P USB_DP USBHUB_DP
net group VDD1P2_DDR: nets VDD1P2_DDR_MON
net group XFP_3V3_PCH_EN_R: nets XFP_3V3_PCH_EN_R

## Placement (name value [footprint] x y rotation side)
C2  0.1uF/16V  [CC0402]  151.55 260.01 90 top
C3  0.1uF/16V  [CC0402]  151.55 257.98 90 top
C4  0.1uF/16V  [CC0402]  266.73 250.54 0 top
C7  0.1uF/16V  [CC0402]  151.55 259 90 top
C8  0.1uF/16V  [CC0402]  151.55 261.03 90 top
C9  0.1uF/16V  [CC0402]  265.71 250.54 0 top
C16  1nF 50V  [CC0402]  227.65 227.11 0 top
C17  0.1uF 16V  [CC0402]  228.8 227.11 180 top
C18  0.1uF 16V  [CC0402]  230.07 227.11 180 top
C19  0.1uF 16V  [CC0402]  232.02 227.11 180 top
C20  0.1uF 16V  [CC0402]  233.11 227.11 180 top
C21  0.1uF 16V  [CC0402]  234.38 227.11 180 top
C22  0.1uF 16V  [CC0402]  235.65 227.11 180 top
C23  0.1uF/16V  [CC0402]  61.61 190.05 270 top
C24  0.1uF/16V  [CC0402]  5.3 189.28 180 top
C25  0.1uF/16V  [CC0402]  70.96 222.92 0 bottom
C27  0.1uF/16V  [CC0402]  4.26 189.27 180 top
C28  0.1uF/16V  [CC0402]  193.36 169.94 180 top
C29  0.1uF 16V  [CC0402]  238.27 225.45 90 top
C30  0.1uF/16V  [CC0402]  191.33 169.97 180 top
C31  1nF /50V  [CC0402]  62.94 184.84 0 top
C32  10uF  [CC0402]  62.94 187.76 0 top
C33  0.1uF/16V  [CC0402]  192.34 169.94 180 top
C34  0.1uF/16V  [CC0402]  190.31 169.97 180 top
C35  0.1uF 16V  [CC0402]  238.21 224.44 90 top
C36  10uF  [CC0603]  63.53 182.4 0 top
C37  0.1uF/16V  [CC0402]  82.81 215.42 180 top
C38  0.1uF/16V  [CC0402]  264.7 250.54 0 top
C39  0.1uF/16V  [CC0402]  263.68 250.54 0 top
C41  10uF  [CC0603]  64.95 182.4 0 top
C42  0.1UF 50V  [CC0603]  89.8 204.26 0 top
C43  22uF/6.3V  [CC0603]  66.5 182.43 0 top
C44  0.1uF/16V  [CC0402]  62.7 223.24 180 top
C45  0.1uF 16V  [CC0402]  238.19 220.89 90 top
C47  0.1uF/16V  [CC0402]  67.64 191.83 180 top
C48  22uF  [CC0603]  80.8 213.54 270 top
C49  10uF/6.3V  [CC0603]  80.79 214.98 270 top
C50  10uF/6.3V  [CC0603]  84.2 210.49 180 top
C52  0.1uF/16V  [CC0402]  82.9 210.67 180 top
C53  0.1uF 16V  [CC0402]  238.21 219.55 90 top
C54  22uF/6.3V  [CC0603]  68.28 182.43 0 top
C55  0.1uF/16V  [CC0402]  167.39 178.58 180 top
C56  10uF/6.3V  [CC0603]  168.73 178.24 0 top
C57  0.1uF/16V  [CC0402]  153.88 244.34 90 top
C58  @10pF  [CC0402]  90.18 214.78 0 top
C59  0.1uF/16V  [CC0402]  45.75 222.86 0 bottom
C60  0.1uF/16V  [CC0402]  68.59 190.81 0 top
C61  0.1uF 16V  [CC0402]  238.21 218.21 90 top
C62  10uF/6.3V  [CC0603]  181.7 199.43 90 top
C63  1nF  [CC0402]  69.54 182.73 180 top
C64  10nF/50V  [CC0402]  69.22 185.65 90 bottom
C68  0.1uF 16V  [CC0402]  238.19 216.95 90 top
C69  0.1uF/16V  [CC0402]  181.37 198.16 90 top
C73  0.1uF/16V  [CC0402]  22.06 178.03 180 top
C74  22nF/16V  [CC0402]  22.95 178.03 0 top
C75  22nF/16V  [CC0402]  24.98 178.03 0 top
C76  0.1uF/16V  [CC0402]  26 178.03 180 top
C77  1uF/25V  [CC0402]  27.02 178.03 180 top
C78  0.01uF/25V  [CC0402]  28.03 178.03 0 top
C79  1uF/25V  [CC0402]  29.05 178.03 180 top
C80  0.1uF/16V  [CC0402]  30.09 178.03 180 top
C81  0.1uF/16V  [CC0402]  31.11 178.03 180 top
C82  10uF/10V  [CC0402]  32.12 178.03 180 top
C83  0.1uF 16V  [CC0402]  238.19 215.68 90 top
C84  0.01uF/25V  [CC0402]  69.59 177.8 0 top
C85  0.01uF/25V  [CC0402]  70.58 177.8 0 top
C86  0.1uF/16V  [CC0402]  54.32 177.77 180 top
C87  1uF/25V  [CC0402]  55.34 177.77 180 top
C88  22nF/16V  [CC0402]  60.42 177.77 0 top
C89  1uF/25V  [CC0402]  61.43 177.77 180 top
C90  1uF/25V  [CC0402]  62.45 177.77 180 top
C91  0.1uF/16V  [CC0402]  63.47 177.77 180 top
C92  0.1uF/16V  [CC0402]  64.48 177.77 180 top
C93  10uF/10V  [CC0402]  65.5 177.77 180 top
C94  1uF/25V  [CC0402]  66.51 177.77 180 top
C95  0.1uF/16V  [CC0402]  67.53 177.77 180 top
C96  0.1uF/16V  [CC0402]  68.55 177.77 180 top
C97  0.1UF 50V  [CC0603]  86.74 220.1 90 top
C99  0.1uF 16V  [CC0402]  238.19 214.41 90 top
C100  10uF/6.3V  [CC0603]  181.66 195.28 270 top
C101  @10pF  [CC0402]  184.25 194.87 90 top
C102  0.1uF/16V  [CC0402]  54.32 175.49 0 top
C104  0.1uF 16V  [CC0402]  236.67 212.64 90 top
C106  0.1uF 16V  [CC0402]  230.45 212.38 90 top
C107  0.1uF 16V  [CC0402]  232.48 212.38 90 top
C108  0.1uF/16V  [CC0402]  162.78 220.06 90 top
C109  10nF 50V  [CC0402]  233.93 212.13 0 top
C110  1uF  [CC0402]  234.92 212.13 180 top
C112  0.1UF 50V  [CC0603]  86.74 218.63 90 top
C113  0.1uF/16V  [CC0402]  75.66 174.47 270 top
C114  22uF  [CC0603]  181.66 193.63 270 top
C115  0.1UF 50V  [CC0603]  123.78 204.35 180 top
C117  0.1uF 16V  [CC0402]  230.45 211.37 90 top
C118  0.1uF 16V  [CC0402]  236.67 211.37 90 top
C119  22nF/16V  [CC0402]  75.66 173.45 90 top
C121  0.1uF/16V  [CC0402]  181.83 192.4 270 top
C122  10uF 6.3V  [CC0603]  234.1 210.12 270 top
C123  10uF 6.3V  [CC0603]  230.32 209.97 90 top
C126  10uF/10V  [CC0402]  75.66 171.42 270 top
C128  1uF/25V  [CC0402]  29.05 170.53 180 top
C129  0.1uF/16V  [CC0402]  230.57 207.68 90 top
C130  1uF/25V  [CC0402]  75.66 170.41 270 top
C131  0.01uF  [CC0402]  203.11 233.53 270 top
C132  1uF/25V  [CC0402]  46.45 170.28 0 top
C133  0.1uF/16V  [CC0402]  47.46 170.28 0 top
C134  0.1uF/16V  [CC0402]  27.14 169.64 0 top
C135  22nF/16V  [CC0402]  28.16 169.64 0 top
C136  10uF  [CC0603]  203.61 235.87 270 top
C137  10pF  [CC0402]  203.11 234.54 90 top
C139  10uF/6.3V  [CC0603]  9.49 167.04 90 top
C140  @10pF/50V  [CC0402]  6.19 167.85 270 top
C142  0.1uF/16V  [CC0402]  75.66 167.36 270 top
C143  0.01uF/25V  [CC0402]  28.54 166.93 270 top
C144  0.1uF/16V  [CC0402]  10.51 168.31 90 top
C145  0.1UF 50V  [CC0603]  129.07 216.55 180 top
C146  2.2UF  [CC0603]  200.17 237.99 90 top
C149  0.1uF/16V  [CC0402]  28.54 165.91 270 top
C151  1uF/25V  [CC0402]  26.38 165.45 90 top
C152  22uF/6.3V  [CC0603]  32.1 165.45 90 top
C153  0.1uF  [CC0402]  199.99 239.24 270 top
C154  1uF/25V  [CC0402]  29.94 165.2 180 top
C157  0.1UF 50V  [CC0603]  85.94 233.53 0 top
C158  22uF/6.3V  [CC0603]  76.37 165.02 0 top
C159  22uF/6.3V  [CC0603]  78.15 165.02 0 top
C161  0.1uF/16V  [CC0402]  27.14 164.06 0 top
C164  1uF/25V  [CC0402]  23.41 163.6 90 top
C165  1uF/25V  [CC0402]  28.16 163.55 180 top
C166  0.01uF/25V  [CC0402]  29.05 163.55 180 top
C167  0.1UF 50V  [CC0603]  129.06 220.09 180 top
C168  0.1uF/16V  [CC0402]  182.93 182.45 180 top
C169  0.01uF/25V  [CC0402]  101.5 160.63 270 bottom
C172  1uF/25V  [CC0402]  32.99 162.41 270 top
C174  0.1UF 50V  [CC0603]  129.12 213.09 180 top
C175  0.1uF/16V  [CC0402]  162.78 221.08 90 top
C176  22uF  [CC0603]  9.49 161.4 0 top
C177  22uF/6.3V  [CC0603]  23.46 161.39 0 top
C178  0.1uF/16V  [CC0402]  28.54 161.26 270 top
C179  1uF/25V  [CC0402]  27.14 161.01 180 top
C182  0.1UF 50V  [CC0603]  85.94 229.78 0 top
C183  0.1uF/16V  [CC0402]  242.98 242.8 90 top
C184  22nF/16V  [CC0402]  28.54 160.12 270 top
C186  22nF/16V  [CC0402]  32.22 159.87 180 top
C188  0.1uF/16V  [CC0402]  212.71 127.84 270 top
C189  1uF/6.3V  [CC0402]  212.71 126.83 270 top
C190  0.1uF/16V  [CC0402]  212.71 125.81 270 top
C191  0.1uF/16V  [CC0402]  212.71 122.76 270 top
C193  1000pF /50V  [CC0402]  123 141.97 90 top
C194  0.1uF/16V  [CC0402]  122.62 139.18 180 top
C195  0.1UF 50V  [CC0603]  140.4 235.26 180 top
C196  0.01uF/25V  [CC0402]  28.11 158.7 0 top
C197  1uF/25V  [CC0402]  29.1 158.7 0 top
C198  0.01uF/25V  [CC0402]  27.14 158.67 0 top
C199  10uF/6.3V  [CC0603]  10.95 161.39 0 top
C200  22nF/16V  [CC0402]  78.58 158.47 180 top
C201  0.1UF 50V  [CC0603]  140.43 228.71 180 top
C202  22uF/6.3V  [CC0603]  104.23 157.77 0 top
C203  1uF/25V  [CC0402]  25.7 157.5 270 top
C204  1uF/25V  [CC0402]  30.37 157.22 90 top
C205  0.1uF/16V  [CC0402]  120.72 134.86 0 top
C206  0.1uF/16V  [CC0402]  10.24 158.68 270 top
C207  10uF  [CC0402]  119.7 134.86 0 top
C208  0.1uF/16V  [CC0402]  7.59 155.61 0 top
C209  0.1uF/16V  [CC0402]  187.6 176.38 90 top
C210  0.1uF/16V  [CC0402]  187.6 175.36 90 top
C211  10uF/10V  [CC0402]  117.41 145.02 180 top
C212  0.1uF/16V  [CC0402]  116.4 145.02 180 top
C213  10uF  [CC0402]  112.94 136.27 270 top
C214  0.1uF/16V  [CC0402]  90.54 152.09 180 top
C215  0.1uF/16V  [CC0402]  91.81 152.09 180 top
C217  0.1uF/16V  [CC0402]  14.38 258.32 90 top
C218  0.1uF/16V  [CC0402]  14.38 257.33 90 top
C219  0.1uF/16V  [CC0402]  209.79 227.57 270 top
C220  0.1uF/16V  [CC0402]  209.79 226.56 270 top
C223  10uF  [CC0402]  112.94 137.28 270 top
C224  @1nF  [CC0402]  73.89 150.76 0 top
C225  1uF/16V  [CC0402]  20.16 150.72 180 top
C226  1uF/16V  [CC0402]  22.44 150.72 180 top
C227  @10pF  [CC0402]  13.55 153.36 90 top
C230  0.1uF/16V  [CC0402]  203.7 120.61 180 top
C231  0.1uF/16V  [CC0402]  112.94 138.3 270 top
C235  0.1uF/16V  [CC0402]  84.78 149.3 90 top
C236  10uF/10V  [CC0402]  115.58 140.37 180 bottom
C237  1uF/6.3V  [CC0402]  201.28 123.78 90 top
C238  0.1uF/16V  [CC0402]  201.28 122.76 90 top
C240  0.1uF/16V  [CC0402]  201.03 132.33 270 top
C244  12pF/50V  [CC0402]  200.01 126.83 90 top
C245  12pF/50V  [CC0402]  200.01 124.8 270 top
C247  0.1uF/16V  [CC0402]  14.38 256.34 90 top
C248  0.1uF/16V  [CC0402]  209.79 225.55 270 top
C249  @10pF/50V  [CC0402]  78.32 142.09 180 top
C250  0.1uF/16V  [CC0402]  98.14 147.9 90 top
C251  1nF  [CC0805]  100.17 145.26 0 top
C252  1nF  [CC0805]  102.2 145.26 0 top
C253  100uF/6.3V  [CC0805]  104.23 145.26 180 top
C254  10uF/6.3V  [CC0805]  106.26 145.26 180 top
C255  10uF/6.3V  [CC0805]  108.3 145.26 180 top
C256  22uF/16V  [CC1206]  249.19 169.26 0 top
C257  22uF/16V  [CC1206]  251.61 169.26 0 top
C258  470uF/2V  [CAP_6D4_2SP_4D3W7D3L2D1H]  112.11 179.04 270 bottom
C259  0.1uF/16V  [CC0402]  14.38 255.35 90 top
C260  0.1uF/16V  [CC0402]  209.79 228.6 270 top
C261  @10uF/16V  [CC0805]  247.01 169.7 0 top
C262  1uF/16V  [CC0402]  27.52 144.37 270 top
C263  0.1uF/16V  [CC0402]  98.14 146.89 90 top
C264  0.1uF/16V  [CC0402]  245.41 169.36 0 top
C265  1uF/16V  [CC0402]  39.72 143.36 90 top
C266  10uF/6.3V  [CC0805]  24.42 143.14 90 top
C267  1uF/16V  [CC0603]  58.77 142.09 0 top
C268  47uF/4V  [CC0603]  40.22 141.32 180 top
C269  10uF/6.3V  [CC0805]  17.75 140.05 270 top
C270  10uF/6.3V  [CC0805]  24.48 140.05 180 top
C271  10uF/6.3V  [CC0805]  56.23 139.55 90 top
C272  10uF/6.3V  [CC0805]  15.33 137.89 90 top
C273  470uF/ 2V  [CAP_6D4_2SP_4D3W7D3L2D1H]  77.44 135.86 270 top
C274  1000pF/50V  [CC0402]  103.34 135.61 90 top
C275  1nF/50V  [CC0402]  163.21 134.8 270 top
C276  0.1uF/16V  [CC0402]  140.14 210.15 90 top
C277  1uF/16V  [CC0402]  6.95 135.1 270 top
C279  1uF/16V  [CC0603]  34.78 192.37 270 top
C280  0.1uF/16V  [CC0402]  248.49 197.46 270 top
C281  22uF/25V  [CC1206]  32.08 186.4 0 top
C282  22uF/25V  [CC1206]  34.37 186.4 0 top
C283  0.1uF/16V  [CC0402]  103.34 133.58 90 top
C284  0.1uF/25V  [CC0402]  36.12 186.4 0 bottom
C285  1uF/16V  [CC0402]  36.05 189.32 0 top
C286  @10pF/50V  [CC0402]  126.65 208.51 270 top
C287  10nF/ 50V  [CC0402]  123.79 163.42 180 bottom
C288  0.1UF/50V  [CC0603]  125.7 163.93 180 top
C289  100uF /6.3V  [CC1206]  121 156.18 0 top
C291  2.2nF/100V  [CC0603]  109.74 131.44 180 top
C292  4.7uF/25V  [CC0805]  160.39 129.51 270 top
C293  0.1uF/25V  [CC0402]  36.12 186.4 180 top
C294  22uF/25V  [CC1206]  32.08 186.4 180 bottom
C295  22uF/25V  [CC1206]  34.37 186.4 180 bottom
C296  @100uF/6.3V  [CC0805]  72.1 128.12 0 top
C297  @100uF/6.3V  [CC0805]  74.13 128.12 0 top
C298  22uF/16V  [CC1206]  256.78 160.57 0 top
C300  22uF/10V  [CC1206]  76.29 127.73 0 top
C301  22uF/25V  [CC1206]  78.58 127.73 180 top
C302  22uF/16V  [CC1206]  222.96 152.98 270 bottom
C303  0.1uF/16V  [CC0402]  264.28 91.83 0 top
C304  0.1uF/16V  [CC0402]  263.27 91.83 0 top
C305  0.1uF/16V  [CC0402]  124.33 169.08 180 top
C306  1nF/50V  [CC0402]  42.27 194.4 0 top
C307  3.3nF /50V  [CC0402]  100.04 126.59 90 top
C308  10nF/ 50V  [CC0402]  138.67 133.53 90 top
C309  4.7uF/16V  [CC0603]  162.17 124.94 0 top
C310  0.1UF/50V  [CC0603]  166.87 124.94 180 top
C311  1nF/50V  [CC0402]  254.1 160.62 0 top
C312  0.1uF/16V  [CC0402]  255.12 160.62 0 top
C313  0.1uF/16V  [CC0402]  243.22 127.59 90 top
C314  470uF/2V/4A  [CAP_6D4_2SP_4D3W7D3L2D1H]  86.55 88.59 90 top
C316  22uF/16V  [CC1206]  222.35 146.52 90 bottom
C317  22uF/16V  [CC1206]  222.96 150.56 270 bottom
C318  10uF /25V  [CC0603]  99.91 124.94 90 top
C319  0.1UF /50V  [CC0603]  138.37 132.32 270 top
C320  10uF/6.3V  [CC0603]  242.02 123.23 270 top
C321  0.1uF/16V  [CC0402]  242.54 121.96 270 top
C322  0.1uF/16V  [CC0402]  223.19 144.31 90 bottom
C323  0.1uF  [CC0402]  45.96 193.13 270 top
C324  1000pF  [CC0402]  120.23 123.04 90 top
C325  100uF /6.3V  [CC1206]  138.37 130.43 270 top
C326  @4700pF  [CC0402]  256.12 161.64 180 bottom
C327  @100uF/6.3V  [CC0805]  72.1 122.4 180 top
C328  @100uF/6.3V  [CC0805]  74.13 122.4 180 top
C329  22uF/10V  [CC1206]  76.29 122.27 180 top
C330  22uF/25V  [CC1206]  78.45 122.27 0 top
C331  47pF/50V  [CC0402]  107.23 122.02 270 top
C332  0.1uF/16V  [CC0402]  236.13 144.31 270 bottom
C333  22uF/6.3V  [CC0805]  235.66 142.78 270 bottom
C334  100uF /6.3V  [CC1206]  138.37 128.14 270 top
C335  680pF/50V  [CC0402]  106.65 120.56 180 top
C336  0.33uF/6.3V  [CC0402]  110.46 120.19 0 top
C337  1uF/16V  [CC0402]  111.47 120.19 0 top
C338  1uF/16V  [CC0402]  114.01 120.19 0 top
C339  0.1uF/16V  [CC0402]  120.23 121 270 top
C340  1000pF/50V  [CC0402]  103.47 120.37 90 top
C341  0.1uF/16V  [CC0402]  266.33 91.84 0 top
C342  0.1uF/16V  [CC0402]  247.25 220.48 0 top
C343  0.1uF/16V  [CC0402]  248.27 220.48 0 top
C344  0.1uF/16V  [CC0402]  31.24 209.81 0 top
C345  0.1uF/16V  [CC0402]  32.25 209.81 0 top
C346  1uF/16V  [CC0603]  63.02 121.26 0 top
C347  0.1uF/16V  [CC0402]  265.3 91.83 0 top
C348  0.1uF/16V  [CC0402]  103.47 118.34 90 top
C349  10uF/6.3V  [CC0805]  62.77 118.4 90 top
C350  100uF /6.3V  [CC1206]  138.37 125.85 270 top
C351  0.1uF/25V  [CC0402]  118.48 178.48 270 bottom
C352  4.7uF/16V  [CC0603]  113.38 117.7 0 top
C353  470uF/2V/4A  [CAP_6D4_2SP_4D3W7D3L2D1H]  112.39 90.78 180 top
C354  0.47uF/16V(10%)  [CC0402]  243.39 163.23 270 top
C355  0.1uF/16V  [CC0402]  243.78 161.79 180 top
C356  8200pF/16V  [CC0402]  243.35 160.32 270 top
C357  1uF/16V  [CC0603]  123.69 179.62 0 top
C358  1uF/16V  [CC0603]  122.29 179.62 0 top
C359  100uF /6.3V  [CC1206]  47.35 180.68 270 top
C360  100uF /6.3V  [CC1206]  47.34 178.34 270 top
C361  22pF  [CC0402]  243.36 164.25 90 top
C362  22uF /25V  [CC1206]  170.75 116.62 180 top
C363  22uF /25V  [CC1206]  172.78 116.62 180 top
C364  22uF /25V  [CC1206]  175.07 116.62 180 top
C365  22uF/25V  [CC1206]  118.86 180.2 90 bottom
C366  1uF/16V  [CC0402]  82.62 102.99 0 bottom
C367  1uF/16V  [CC0402]  81.6 102.99 0 bottom
C368  1uF/16V  [CC0402]  80.58 102.99 0 bottom
C369  1uF/16V  [CC0402]  79.57 102.99 0 bottom
C370  10nF/ 50V  [CC0402]  47.02 182.41 270 bottom
C371  @100uF /6.3V  [CC1206]  138.37 123.57 270 top
C372  47uF/4V  [CC0603]  63.08 115.67 90 top
C373  0.1UF/50V  [CC0603]  47.97 182.47 270 top
C374  1uF/16V  [CC0402]  65.88 115.16 180 top
C375  470uF/2V/4A  [CAP_6D4_2SP_4D3W7D3L2D1H]  70.45 115.16 270 top
C376  0.1uF/25V  [CC0402]  169.04 115.09 0 top
C377  0.1uF/16V  [CC0402]  13.3 111.86 90 top
C378  470uF/ 2V  [CAP_6D4_2SP_4D3W7D3L2D1H]  77.44 114.15 90 top
C379  470uF/ 2V  [CAP_6D4_2SP_4D3W7D3L2D1H]  82.39 114.15 90 top
C380  22uF/25V  [CC1206]  118.89 180.21 270 top
C381  @100uF /6.3V  [CC1206]  138.4 121.31 270 top
C382  0.1uF/16V  [CC0402]  13.3 110.72 90 top
C383  10uF/6.3V  [CC0805]  9.19 113.18 270 top
C387  22uF/16V  [CC0805]  160.17 110.89 0 top
C388  22uF/16V  [CC0805]  162.2 110.89 0 top
C389  22uF/16V  [CC0805]  167.28 110.89 0 top
C390  22uF/16V  [CC0805]  169.31 110.89 0 top
C391  10uF/16V  [CC0805]  171.35 110.89 0 top
C392  3.3nF /50V  [CC0402]  98.9 111.61 90 top
C393  1uF/16V  [CC0603]  158.39 110.64 0 top
C394  100uF /6.3V  [CC1206]  138.4 119.02 270 top
C395  1uF/16V  [CC0402]  61.81 110.97 0 top
C396  1uF/16V  [CC0402]  62.83 110.97 0 top
C397  1uF/16V  [CC0402]  63.85 110.97 0 top
C398  1uF/16V  [CC0402]  64.86 110.97 0 top
C399  1uF/16V  [CC0402]  65.88 110.97 0 top
C400  1uF/16V  [CC0402]  66.89 110.97 0 top
C401  0.1uF/16V  [CC0402]  157.12 110.13 0 top
C402  0.1uF/16V  [CC0402]  172.87 110.13 0 top
C403  10uF/6.3V  [CC0805]  9.19 111.15 270 top
C404  0.1uF/16V  [CC0402]  14.57 106.14 90 top
C405  10uF /25V  [CC0603]  98.57 110.39 90 top
C406  0.1uF/16V  [CC0402]  14.57 105.13 90 top
C407  1uF/16V  [CC0402]  6.44 109.57 0 top
C408  22uF/25V  [CC1206]  118.84 109.32 0 top
C409  22uF/25V  [CC1206]  121.25 109.32 0 top
C411  0.1uF/25V  [CC0402]  113.38 108.81 270 top
C412  470uF/2V/4A  [CAP_6D4_2SP_4D3W7D3L2D1H]  111.8 88.03 90 bottom
C413  0.1uF/16V  [CC0402]  16.35 108.43 90 top
C415  0.1uF/16V  [CC0402]  16.35 107.41 90 top
C416  10uF/6.3V  [CC0805]  62.07 107.03 180 top
C417  0.1uF/16V  [CC0402]  16.35 114.88 90 top
C420  0.1uF/16V  [CC0402]  245.22 220.48 0 top
C421  0.1uF/16V  [CC0402]  246.24 220.48 0 top
C422  0.1uF/16V  [CC0402]  29.12 209.79 0 top
C423  0.1uF/16V  [CC0402]  30.13 209.79 0 top
C424  0.1uF/16V  [CC0402]  16.32 113.87 90 top
C425  10uF/6.3V  [CC0805]  64.48 105 0 top
C426  1uF/16V  [CC0402]  6.44 104.49 180 top
C427  10uF/6.3V  [CC0805]  9.26 104.26 270 top
C428  10uF/10V  [CC0402]  95.47 104.11 270 top
C429  22uF/25V  [CC1206]  118.84 103.99 180 top
C430  22uF/25V  [CC1206]  121.25 103.99 180 top
C431  470uF/2V/4A  [CAP_6D4_2SP_4D3W7D3L2D1H]  81.25 103.86 90 top
C432  0.1uF/16V  [CC0402]  14.57 103.35 90 top
C433  1uF/10V  [CC0402]  200.11 96.19 0 top
C435  0.1uF/16V  [CC0402]  95.47 103.1 270 top
C436  0.1uF/16V  [CC0402]  14.57 102.33 90 top
C437  0.1uF10V  [CC0402]  201.12 96.19 0 top
C438  10uF/6.3V  [CC0805]  9.26 102.23 270 top
C439  0.1uF/16V  [CC0402]  90.14 102.08 270 top
C440  47uF/4V  [CC0603]  6.44 101.95 180 top
C441  0.1uF/10V  [CC0402]  202.14 96.19 0 top
C443  470uF/2V/4A  [CAP_6D4_2SP_4D3W7D3L2D1H]  72.99 101.19 0 top
C444  10uF  [CC0402]  90.14 101.06 270 top
C446  4.7uF/25V  [CC0805]  119.6 100.61 90 top
C447  1uF/16V  [CC0603]  119.65 101.26 270 bottom
C448  0.1uF/50V  [CC0603]  108.55 100.43 90 top
C449  0.1uF/16V  [CC0402]  147.21 100.36 90 top
C451  0.1uF/16V  [CC0402]  90.14 100.05 270 top
C452  100uF /6.3V  [CC1206]  101.31 99.79 0 top
C453  100uF /6.3V  [CC1206]  103.65 99.79 0 top
C454  47uF/4V  [CC0603]  15.43 99.67 90 top
C455  0.1UF 50V  [CC0603]  155.72 98.19 270 top
C458  470uF/2V/4A  [CAP_6D4_2SP_4D3W7D3L2D1H]  64.61 97.89 90 top
C459  10uF/10V  [CC0402]  99.66 97.64 180 top
C461  1uF/16V  [CC0402]  6.7 97.38 270 top
C462  1nF  [CC0402]  147.09 96.42 90 top
C463  47uF/4V  [CC0603]  15.36 97.13 90 top
C464  0.1uF  [CC0402]  213.44 101.96 90 top
C465  0.1uF  [CC0402]  213.44 102.97 90 top
C466  1uF  [CC0402]  213.44 103.99 90 top
C467  1000pF  [CC0402]  90.52 96.62 180 top
C468  1uF  [CC0402]  203.26 101.79 270 top
C469  0.1uF  [CC0402]  203.26 100.78 270 top
C470  0.1uF  [CC0402]  203.26 99.76 270 top
C471  1uF/16V  [CC0402]  6.7 96.37 270 top
C472  1uF  [CC0402]  214.52 108.27 90 top
C473  1uF  [CC0402]  211.09 108.27 270 top
C474  1uF/16V  [CC0402]  6.7 95.35 270 top
C475  10uF/6.3V  [CC0805]  15.33 95.35 90 top
C476  1uF/16V  [CC0603]  154.96 94.38 180 top
C477  1uF  [CC0402]  214.52 109.29 90 top
C478  1uF/16V  [CC0402]  6.7 94.33 270 top
C479  10uF/16V  [CC0805]  151.15 92.86 0 top
C481  0.1uF/16V  [CC0402]  98.01 93.57 0 top
C482  10uF/10V  [CC0402]  99.03 93.57 0 top
C483  @1nF  [CC0402]  3.67 148.29 0 bottom
C484  0.1uF/16V  [CC0402]  243.81 132.81 90 top
C485  0.1uF/16V  [CC0402]  171.42 206.35 90 top
C486  0.1uF/16V  [CC0402]  171.42 207.36 90 top
C487  10uF  [CC0805]  214.77 110.94 270 top
C488  10uF  [CC0805]  210.96 110.94 90 top
C489  0.1uF 16V  [CC0402]  154.71 91.84 0 top
C493  10nF/ 50V  [CC0402]  156.23 90.83 90 top
C495  470uF/2V/4A  [CAP_6D4_2SP_4D3W7D3L2D1H]  31.59 91.54 180 top
C496  470uF/2V/4A  [CAP_6D4_2SP_4D3W7D3L2D1H]  41.24 91.54 0 top
C497  470uF/2V/4A  [CAP_6D4_2SP_4D3W7D3L2D1H]  57.55 91.54 180 top
C498  1nF/50V  [CC0805]  18.89 91.41 180 top
C499  1nF/50V  [CC0805]  20.92 91.41 180 top
C500  1nF/50V  [CC0805]  23.08 91.41 180 top
C501  10uF/6.3V  [CC0805]  25.37 91.41 180 top
C502  10uF/6.3V  [CC0805]  47.34 91.16 180 top
C503  10uF/6.3V  [CC0805]  49.5 91.16 180 top
C504  1nF/50V  [CC0805]  51.53 91.16 180 top
C506  0.1UF /50V  [CC0603]  155.74 89.58 270 top
C508  1nF/50V  [CC0805]  238.81 101.41 270 top
C509  100pF/50V  [CC0603]  238.71 97.59 270 top
C511  10uF/16V  [CC0805]  238.81 103.44 90 top
C512  10nF/50V  [CC0402]  238.61 96.3 90 top
C513  100uF/6.3V  [CC1206]  154.73 87.4 270 top
C514  10uF/16V  [CC0805]  238.81 99.36 90 top
C516  0.1uF/16V  [CC0402]  171.42 205.33 90 top
C517  22uF/6.3V  [CC0603]  123.39 72.4 0 top
C518  0.1uF  [CC0402]  241.84 71.47 270 bottom
C519  22uF/6.3V  [CC0603]  162.06 72.4 0 top
C521  0.1uF/16V  [CC0402]  171.42 204.32 90 top
C522  0.1uF/10V  [CC0402]  240.25 93.64 90 top
C523  0.1uF/16V  [CC0402]  87.98 75.98 270 top
C524  0.1uF/16V  [CC0402]  87.98 77 270 top
C525  0.1uF/10V  [CC0402]  240.25 92.62 90 top
C528  0.1uF/10V  [CC0402]  240.25 91.6 90 top
C529  0.1uF/16V  [CC0402]  180.13 68.74 180 bottom
C530  22uF/6.3V  [CC0603]  67.49 72.4 0 top
C531  22uF/6.3V  [CC0603]  80 72.4 0 top
C532  22uF/6.3V  [CC0603]  110.81 72.4 0 top
C533  22uF/6.3V  [CC0603]  131.52 72.28 0 top
C534  22uF/6.3V  [CC0603]  149.55 72.4 0 top
C535  22uF/6.3V  [CC0603]  174.69 72.4 0 top
C536  22uF/6.3V  [CC0603]  187.33 72.4 0 top
C538  1uF/16V  [CC0603]  240.44 69 270 bottom
C539  22uF/6.3V  [CC0603]  29.85 72.69 0 top
C540  22uF/6.3V  [CC0603]  42.4 72.4 0 top
C541  22uF/6.3V  [CC0603]  54.98 72.4 0 top
C542  0.1uF/16V  [CC0402]  229.17 130.88 0 bottom
C544  0.1uF/16V  [CC0402]  110.29 76.31 90 top
C545  0.1uF/16V  [CC0402]  28.85 68.87 0 top
C546  0.1uF/16V  [CC0402]  47.84 68.74 180 bottom
C547  0.1uF/16V  [CC0402]  53.94 68.87 0 top
C548  0.1uF/16V  [CC0402]  228.18 130.88 0 bottom
C549  0.1uF/16V  [CC0402]  110.29 75.27 90 top
C550  0.1uF/16V  [CC0402]  66.45 68.87 180 bottom
C551  0.1uF/16V  [CC0402]  66.45 68.87 0 top
C552  0.1uF/16V  [CC0402]  78.95 68.87 180 bottom
C553  0.1uF/16V  [CC0402]  78.95 68.87 0 top
C554  0.1uF/16V  [CC0402]  109.77 68.87 0 top
C555  0.1uF/16V  [CC0402]  116.25 68.74 0 top
C556  0.1uF/16V  [CC0402]  128.82 68.74 180 bottom
C557  0.1uF/16V  [CC0402]  122.35 68.87 180 bottom
C558  0.1uF/16V  [CC0402]  130.48 68.75 180 bottom
C559  0.1uF/16V  [CC0402]  130.48 68.75 0 top
C560  0.1uF/16V  [CC0402]  148.51 68.87 0 top
C561  0.1uF/16V  [CC0402]  148.51 68.87 180 bottom
C562  0.1uF/16V  [CC0402]  161.02 68.87 180 bottom
C563  0.1uF/16V  [CC0402]  167.49 68.74 0 top
C564  0.1uF/16V  [CC0402]  173.65 68.87 0 top
C565  0.1uF/16V  [CC0402]  192.77 68.74 180 bottom
C566  0.1uF/16V  [CC0402]  186.29 68.87 180 bottom
C569  0.1uF/16V  [CC0402]  28.85 68.87 180 bottom
C570  0.1uF/16V  [CC0402]  47.84 68.74 0 top
C571  0.1uF/16V  [CC0402]  53.94 68.87 180 bottom
C573  2.2uF(25V/10%)  [CC0603]  244.44 64.91 270 bottom
C574  0.1uF/16V  [CC0402]  20.27 71.35 180 top
C575  0.1uF/16V  [CC0402]  21.32 71.36 180 top
C576  0.1uF/16V  [CC0402]  22.32 71.38 180 top
